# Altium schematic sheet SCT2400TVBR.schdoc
size 127 x 101 mm
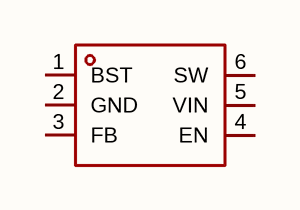
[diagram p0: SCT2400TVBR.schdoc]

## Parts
U?  sct2400tvbr  [TSOT-23-6_L2.9-W1.6-P0.95-LS2.8-BR]  (value not drawn)

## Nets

Not connected (* = marked no-connect by the designer): U? 1(BST) 2(GND) 3(FB) 4(EN) 5(VIN) 6(SW)

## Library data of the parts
U? = sct2400tvbr: 功能类型:降压型;工作电压:4.5V~40V;输出电压:-;输出电流:600mA;输出类型:可调;; Manufacturer: SCT(芯洲科技); AddInBom: yes; ModelId: 2c4039b5b88644c1bda4b4ba9e971667; ModelName: TSOT-23-6_L2.9-W1.6-H1.1-LS2.8-P0.95; ModelTransform: 110.45568,114.173,0,180,0,0,-0.005,-0.0005,0; Function: 降压型; Output Current: 600mA; Frequency - Switching: 2MHz; Synchronous Rectifier: 是; Number of Outputs: 1; Topology: 降压式; Quiescent Current: 90uA; Switch tube (built-in/external): 内置; Output Type: 可调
